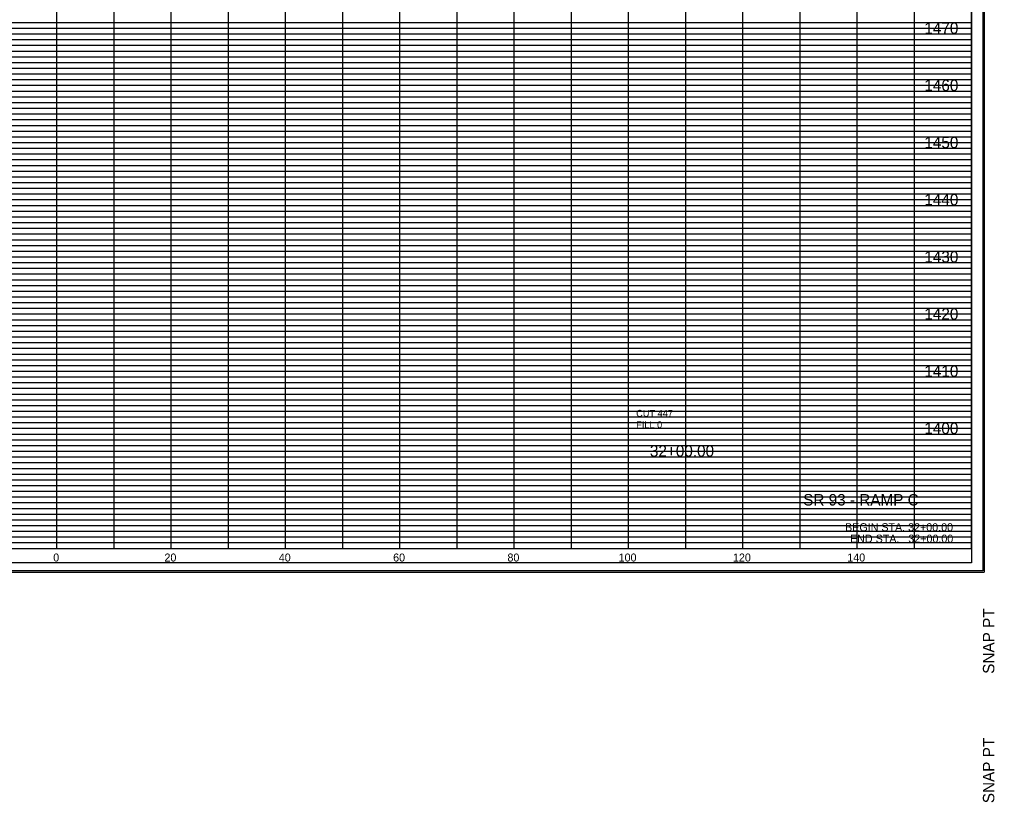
# Model space of a CAD drawing. Extents: x 980 to 2064, y 978 to 2267.
# Drawn here: x 1153.4 to 1324, y 1995.5 to 2132.5 of the extents above; entities that cross this region are included whole.
import ezdxf

# ---------------------------------------------------------------- set-up
doc = ezdxf.new("R2010")
doc.units = 0
for name, color, linetype in [('Default', 7, 'Continuous'), ('DESIGN - SHEET - Corner Text', 7, 'Continuous'), ('DESIGN - SHEET - Light Grid', 7, 'Continuous'), ('DESIGN - SHEET - Linework', 7, 'Continuous'), ('DESIGN - SHEET - Plot Shape', 7, 'Continuous'), ('DESIGN - TYPICAL - Text', 7, 'Continuous')]:
    doc.layers.add(name, color=color, linetype=linetype)

# ---------------------------------------------------------------- blocks, each defined once
blk = doc.blocks.new('XSTSHT')
at = {"layer": 'DESIGN - SHEET - Light Grid'}
for p, q in [((8, 9.2), (16, 9.2)), ((8, 9.1), (16, 9.1)), ((16, 9.2), (24, 9.2)), ((16, 9.1), (24, 9.1)), ((24, 9.2), (32, 9.2)), ((24, 9.1), (32, 9.1)), ((8, 8.9), (16, 8.9)), ((16, 8.9), (24, 8.9)), ((24, 8.9), (32, 8.9)), ((8, 8.8), (16, 8.8)), ((8, 8.7), (16, 8.7)), ((16, 8.8), (24, 8.8)), ((16, 8.7), (24, 8.7)), ((24, 8.8), (32, 8.8)), ((24, 8.7), (32, 8.7)), ((8, 8.6), (16, 8.6)), ((16, 8.6), (24, 8.6)), ((24, 8.6), (32, 8.6)), ((8, 8.5), (16, 8.5)), ((8, 8.4), (16, 8.4)), ((16, 8.5), (24, 8.5)), ((16, 8.4), (24, 8.4)), ((24, 8.5), (32, 8.5)), ((24, 8.4), (32, 8.4)), ((8, 8.3), (16, 8.3)), ((8, 8.2), (16, 8.2)), ((16, 8.3), (24, 8.3)), ((16, 8.2), (24, 8.2)), ((24, 8.3), (32, 8.3)), ((24, 8.2), (32, 8.2)), ((8, 8.1), (16, 8.1)), ((16, 8.1), (24, 8.1)), ((24, 8.1), (32, 8.1)), ((8, 7.9), (16, 7.9)), ((16, 7.9), (24, 7.9)), ((24, 7.9), (32, 7.9)), ((8, 7.8), (16, 7.8)), ((8, 7.7), (16, 7.7)), ((16, 7.8), (24, 7.8)), ((16, 7.7), (24, 7.7)), ((24, 7.8), (32, 7.8)), ((24, 7.7), (32, 7.7)), ((8, 7.6), (16, 7.6)), ((16, 7.6), (24, 7.6)), ((24, 7.6), (32, 7.6)), ((8, 7.5), (16, 7.5)), ((8, 7.4), (16, 7.4)), ((16, 7.5), (24, 7.5)), ((16, 7.4), (24, 7.4)), ((24, 7.5), (32, 7.5)), ((24, 7.4), (32, 7.4)), ((8, 7.3), (16, 7.3)), ((8, 7.2), (16, 7.2)), ((16, 7.3), (24, 7.3)), ((16, 7.2), (24, 7.2)), ((24, 7.3), (32, 7.3)), ((24, 7.2), (32, 7.2)), ((8, 7.1), (16, 7.1)), ((16, 7.1), (24, 7.1)), ((24, 7.1), (32, 7.1)), ((8, 6.9), (16, 6.9)), ((16, 6.9), (24, 6.9)), ((24, 6.9), (32, 6.9)), ((8, 6.8), (16, 6.8)), ((8, 6.7), (16, 6.7)), ((16, 6.8), (24, 6.8)), ((16, 6.7), (24, 6.7)), ((24, 6.8), (32, 6.8)), ((24, 6.7), (32, 6.7)), ((8, 6.6), (16, 6.6)), ((8, 6.5), (16, 6.5)), ((16, 6.6), (24, 6.6)), ((16, 6.5), (24, 6.5)), ((24, 6.6), (32, 6.6)), ((24, 6.5), (32, 6.5)), ((8, 6.4), (16, 6.4)), ((16, 6.4), (24, 6.4)), ((24, 6.4), (32, 6.4)), ((8, 6.3), (16, 6.3)), ((8, 6.2), (16, 6.2)), ((16, 6.3), (24, 6.3)), ((16, 6.2), (24, 6.2)), ((24, 6.3), (32, 6.3)), ((24, 6.2), (32, 6.2)), ((8, 6.1), (16, 6.1)), ((16, 6.1), (24, 6.1)), ((24, 6.1), (32, 6.1)), ((8, 5.9), (16, 5.9)), ((8, 5.8), (16, 5.8)), ((16, 5.9), (24, 5.9)), ((16, 5.8), (24, 5.8)), ((24, 5.9), (32, 5.9)), ((24, 5.8), (32, 5.8)), ((8, 5.7), (16, 5.7)), ((16, 5.7), (24, 5.7)), ((24, 5.7), (32, 5.7)), ((8, 5.6), (16, 5.6)), ((8, 5.5), (16, 5.5)), ((16, 5.6), (24, 5.6)), ((16, 5.5), (24, 5.5)), ((24, 5.6), (32, 5.6)), ((24, 5.5), (32, 5.5)), ((8, 5.4), (16, 5.4)), ((8, 5.3), (16, 5.3)), ((16, 5.4), (24, 5.4)), ((16, 5.3), (24, 5.3)), ((24, 5.4), (32, 5.4)), ((24, 5.3), (32, 5.3)), ((8, 5.2), (16, 5.2)), ((16, 5.2), (24, 5.2)), ((24, 5.2), (32, 5.2)), ((8, 5.1), (16, 5.1)), ((16, 5.1), (24, 5.1)), ((24, 5.1), (32, 5.1)), ((8, 4.9), (16, 4.9)), ((8, 4.8), (16, 4.8)), ((16, 4.9), (24, 4.9)), ((16, 4.8), (24, 4.8)), ((24, 4.9), (32, 4.9)), ((24, 4.8), (32, 4.8)), ((8, 4.7), (16, 4.7)), ((16, 4.7), (24, 4.7)), ((24, 4.7), (32, 4.7)), ((8, 4.6), (16, 4.6)), ((8, 4.5), (16, 4.5)), ((16, 4.6), (24, 4.6)), ((16, 4.5), (24, 4.5)), ((24, 4.6), (32, 4.6)), ((24, 4.5), (32, 4.5)), ((8, 4.4), (16, 4.4)), ((8, 4.3), (16, 4.3)), ((16, 4.4), (24, 4.4)), ((16, 4.3), (24, 4.3)), ((24, 4.4), (32, 4.4)), ((24, 4.3), (32, 4.3)), ((8, 4.2), (16, 4.2)), ((8, 4.1), (16, 4.1)), ((16, 4.2), (24, 4.2)), ((16, 4.1), (24, 4.1)), ((24, 4.2), (32, 4.2)), ((24, 4.1), (32, 4.1)), ((8, 3.9), (16, 3.9)), ((8, 3.8), (16, 3.8)), ((16, 3.9), (24, 3.9)), ((16, 3.8), (24, 3.8)), ((24, 3.9), (32, 3.9)), ((24, 3.8), (32, 3.8)), ((8, 3.7), (16, 3.7)), ((8, 3.6), (16, 3.6)), ((16, 3.7), (24, 3.7)), ((16, 3.6), (24, 3.6)), ((24, 3.7), (32, 3.7)), ((24, 3.6), (32, 3.6)), ((8, 3.5), (16, 3.5)), ((16, 3.5), (24, 3.5)), ((24, 3.5), (32, 3.5)), ((8, 3.4), (16, 3.4)), ((8, 3.3), (16, 3.3)), ((16, 3.4), (24, 3.4)), ((16, 3.3), (24, 3.3)), ((24, 3.4), (32, 3.4)), ((24, 3.3), (32, 3.3)), ((8, 3.2), (16, 3.2)), ((8, 3.1), (16, 3.1)), ((16, 3.2), (24, 3.2)), ((16, 3.1), (24, 3.1)), ((24, 3.2), (32, 3.2)), ((24, 3.1), (32, 3.1)), ((8, 2.9), (16, 2.9)), ((16, 2.9), (24, 2.9)), ((24, 2.9), (32, 2.9)), ((8, 2.8), (16, 2.8)), ((16, 2.8), (24, 2.8)), ((24, 2.8), (32, 2.8)), ((8, 2.7), (16, 2.7)), ((8, 2.6), (16, 2.6)), ((16, 2.7), (24, 2.7)), ((16, 2.6), (24, 2.6)), ((24, 2.7), (32, 2.7)), ((24, 2.6), (32, 2.6)), ((8, 2.5), (16, 2.5)), ((8, 2.4), (16, 2.4)), ((16, 2.5), (24, 2.5)), ((16, 2.4), (24, 2.4)), ((24, 2.5), (32, 2.5)), ((24, 2.4), (32, 2.4)), ((8, 2.3), (16, 2.3)), ((16, 2.3), (24, 2.3)), ((24, 2.3), (32, 2.3)), ((8, 2.2), (16, 2.2)), ((8, 2.1), (16, 2.1)), ((16, 2.2), (24, 2.2)), ((16, 2.1), (24, 2.1)), ((24, 2.2), (32, 2.2)), ((24, 2.1), (32, 2.1)), ((8, 1.9), (16, 1.9)), ((16, 1.9), (24, 1.9)), ((24, 1.9), (32, 1.9)), ((8, 1.8), (16, 1.8)), ((16, 1.8), (24, 1.8)), ((24, 1.8), (32, 1.8)), ((8, 1.7), (16, 1.7)), ((8, 1.6), (16, 1.6)), ((16, 1.7), (24, 1.7)), ((16, 1.6), (24, 1.6)), ((24, 1.7), (32, 1.7)), ((24, 1.6), (32, 1.6)), ((8, 1.5), (16, 1.5)), ((8, 1.4), (16, 1.4)), ((16, 1.5), (24, 1.5)), ((16, 1.4), (24, 1.4)), ((24, 1.5), (32, 1.5)), ((24, 1.4), (32, 1.4)), ((8, 1.3), (16, 1.3)), ((8, 1.2), (16, 1.2)), ((16, 1.3), (24, 1.3)), ((16, 1.2), (24, 1.2)), ((24, 1.3), (32, 1.3)), ((24, 1.2), (32, 1.2)), ((8, 1.1), (16, 1.1)), ((16, 1.1), (24, 1.1)), ((24, 1.1), (32, 1.1)), ((8, 0.9), (16, 0.9)), ((16, 0.9), (24, 0.9)), ((24, 0.9), (32, 0.9)), ((8, 0.8), (16, 0.8)), ((8, 0.7), (16, 0.7)), ((16, 0.8), (24, 0.8)), ((16, 0.7), (24, 0.7)), ((24, 0.8), (32, 0.8)), ((24, 0.7), (32, 0.7)), ((8, 0.6), (16, 0.6)), ((16, 0.6), (24, 0.6)), ((24, 0.6), (32, 0.6)), ((8, 0.5), (16, 0.5)), ((8, 0.4), (16, 0.4)), ((16, 0.5), (24, 0.5)), ((16, 0.4), (24, 0.4)), ((24, 0.5), (32, 0.5)), ((24, 0.4), (32, 0.4)), ((8, 0.3), (16, 0.3)), ((8, 0.2), (16, 0.2)), ((16, 0.3), (24, 0.3)), ((16, 0.2), (24, 0.2)), ((24, 0.3), (32, 0.3)), ((24, 0.2), (32, 0.2)), ((8, 0.1), (16, 0.1)), ((16, 0.1), (24, 0.1)), ((24, 0.1), (32, 0.1))]:
    blk.add_line(p, q, dxfattribs=at)
at = {"layer": 'DESIGN - SHEET - Linework'}
for p, q in [((32.217, 21.414), (32.217, -0.414)), ((16, 0), (16, 21)), ((17, 0), (17, 21)), ((18, 0), (18, 21)), ((19, 0), (19, 21)), ((20, 0), (20, 21)), ((21, 0), (21, 21)), ((22, 0), (22, 21)), ((23, 0), (23, 21)), ((24, 0), (24, 21)), ((25, 0), (25, 21)), ((26, 0), (26, 21)), ((27, 0), (27, 21)), ((28, 0), (28, 20)), ((29, 0), (29, 20)), ((30, 0), (30, 20)), ((31, 0), (31, 20)), ((0, 9), (32, 9)), ((0, 8), (32, 8)), ((0, 7), (32, 7)), ((0, 6), (32, 6)), ((0, 5), (32, 5)), ((0, 4), (32, 4)), ((0, 3), (32, 3)), ((0, 2), (32, 2)), ((0, 1), (32, 1)), ((-1.823, -0.414), (32.217, -0.414))]:
    blk.add_line(p, q, dxfattribs=at)
blk.add_lwpolyline([(0, 21), (0, 0), (32, 0), (32, 21), (0, 21)], dxfattribs=at)
at = {"layer": 'DESIGN - SHEET - Plot Shape'}
for points in [[(-1.803, 21.394), (32.197, 21.394), (32.197, -0.394), (-1.803, -0.394)], [(-0.85, 21), (32, 21), (32, -0.25), (-0.85, -0.25)]]:
    blk.add_lwpolyline(points, close=True, dxfattribs=at)
at = {"layer": 'DESIGN - SHEET - Corner Text'}
for s, p in [('  SNAP PT', (32.397, 21.394)), ('SNAP PT  ', (32.397, -2.194))]:
    blk.add_text(s, height=0.2, rotation=90, dxfattribs=at).set_placement(p)

msp = doc.modelspace()

# ---------------------------------------------------------------- block references
at = {"layer": 'Default', "xscale": 10, "yscale": 10}
for p in [(1000, 2040), (1000, 1780)]:
    msp.add_blockref('XSTSHT', p, dxfattribs=at)

# ---------------------------------------------------------------- texts
at = {"layer": 'Default'}
for s, height, p in [('     1470     ', 2, (1308.01, 2130)), ('     1460     ', 2, (1308.01, 2120)), ('     1450     ', 2, (1308.01, 2110)), ('     1440     ', 2, (1308.01, 2100)), ('     1430     ', 2, (1308.01, 2090)), ('     1420     ', 2, (1308.01, 2080)), ('     1410     ', 2, (1308.01, 2070)), ('     1400     ', 2, (1308.01, 2060)), ('     32+00.00     ', 2, (1260, 2056.04)), ('     0     ', 1.4, (1156.74, 2037.7)), ('     0     ', 1.4, (1156.74, 2037.7)), ('     20     ', 1.4, (1176.2, 2037.7)), ('     40     ', 1.4, (1196.2, 2037.7)), ('     60     ', 1.4, (1216.2, 2037.7)), ('     80     ', 1.4, (1236.2, 2037.7)), ('     100     ', 1.4, (1255.65, 2037.7)), ('     120     ', 1.4, (1275.65, 2037.7)), ('     140     ', 1.4, (1295.65, 2037.7))]:
    msp.add_text(s, height=height, dxfattribs=at).set_placement(p)
at = {"layer": 'DESIGN - SHEET - Corner Text'}
for s, height, p in [('SR 93 - RAMP C', 2, (1290.53, 2047.5)), ('BEGIN STA. 32+00.00', 1.4, (1297.86, 2043)), ('END STA.   32+00.00', 1.4, (1298.73, 2041))]:
    msp.add_text(s, height=height, dxfattribs=at).set_placement(p)
at = {"layer": 'DESIGN - TYPICAL - Text'}
for s, p in [('CUT 447', (1261.32, 2063.03)), ('FILL 0', (1261.32, 2061.03))]:
    msp.add_text(s, height=1.2, dxfattribs=at).set_placement(p)

doc.saveas('drawing.dxf')
